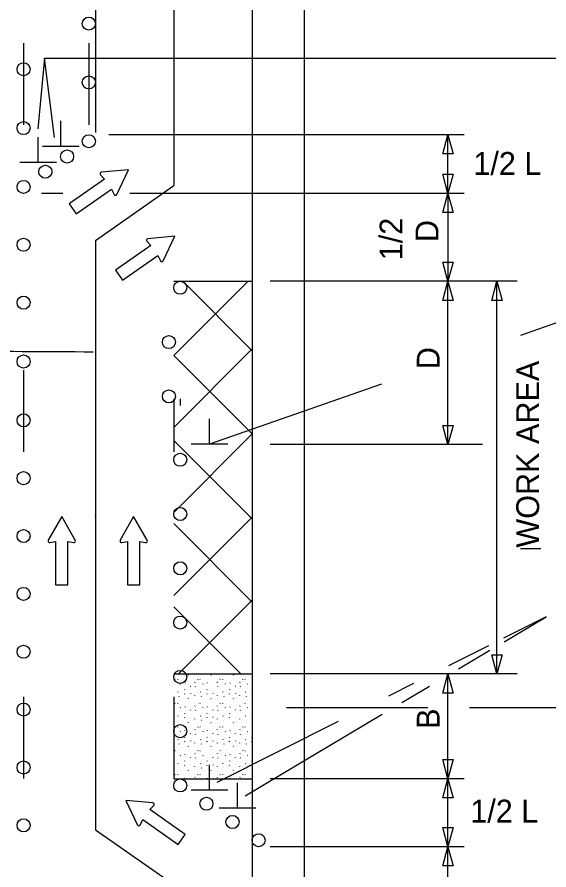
# Model space of a CAD drawing. Extents: x 16765 to 18475, y 6981 to 8262.
# Drawn here: x 17041.1 to 17204, y 7635.5 to 7896.5 of the extents above; entities that cross this region are included whole.
import ezdxf

# ---------------------------------------------------------------- set-up
doc = ezdxf.new("R2010")
doc.units = 0
for name, color, linetype in [('ALI_LEGAL_EX', 7, 'Continuous'), ('MT_SCRATCH_LEVEL_A', 7, 'Continuous'), ('MT_SCRATCH_LEVEL_E', 7, 'Continuous'), ('PAVT_EDGE_EX', 7, 'Continuous'), ('TRAFFIC_SIGNS_PR', 7, 'Continuous'), ('TYPICAL_TEXT_DIMEN_PR', 7, 'Continuous')]:
    doc.layers.add(name, color=color, linetype=linetype)

msp = doc.modelspace()

# ---------------------------------------------------------------- linework, layer by layer
at = {"layer": 'ALI_LEGAL_EX'}
for points in [[(17043.08, 7888.47), (17043.08, 7863.47)], [(17063.08, 7888.47), (17063.08, 7863.47)], [(17089.08, 7888.47), (17089.08, 7863.81)], [(17043.08, 7788.47), (17043.08, 7763.47)], [(17089.08, 7779.65), (17089.08, 7763.47)], [(17091.08, 7779.65), (17091.08, 7777.65)], [(17043.08, 7688.47), (17043.08, 7663.47)], [(17089.08, 7688.47), (17089.08, 7663.47)]]:
    msp.add_lwpolyline(points, dxfattribs=at)
at = {"layer": 'MT_SCRATCH_LEVEL_A'}
for p, q in [((17089.08, 7815.65), (17113.08, 7815.65)), ((17089.09, 7792.92), (17111.83, 7815.65)), ((17113.08, 7794.39), (17091.82, 7815.65)), ((17089.08, 7770.93), (17113.08, 7794.93)), ((17113.08, 7768.93), (17089.08, 7792.93)), ((17089.08, 7744.93), (17113.08, 7768.93)), ((17113.08, 7742.94), (17089.08, 7766.94)), ((17089.08, 7719.48), (17113.08, 7743.48)), ((17113.08, 7717.48), (17089.08, 7741.48)), ((17090.54, 7695.48), (17113.08, 7718.02)), ((17109.63, 7695.48), (17089.08, 7716.03)), ((17089.08, 7695.48), (17113.08, 7695.48)), ((17089.46, 7693.88), (17089.51, 7693.8)), ((17090.19, 7693.85), (17090.24, 7693.78)), ((17093.56, 7695.12), (17093.61, 7695.24)), ((17096.34, 7693.88), (17096.39, 7693.8)), ((17097.08, 7693.85), (17097.13, 7693.78)), ((17100.45, 7695.12), (17100.5, 7695.24)), ((17103.23, 7693.88), (17103.28, 7693.8)), ((17103.97, 7693.85), (17104.02, 7693.78)), ((17107.33, 7695.12), (17107.39, 7695.24)), ((17110.12, 7693.88), (17110.17, 7693.8)), ((17110.85, 7693.85), (17110.91, 7693.78)), ((17091.06, 7692.47), (17091.11, 7692.4)), ((17092.51, 7692.62), (17092.56, 7692.74)), ((17094.13, 7691.8), (17094.18, 7691.72)), ((17095.58, 7692.92), (17095.63, 7693.04)), ((17095.66, 7691.66), (17095.71, 7691.58)), ((17097.95, 7692.47), (17098, 7692.4)), ((17099.4, 7692.62), (17099.45, 7692.74)), ((17101.02, 7691.8), (17101.07, 7691.72)), ((17102.47, 7692.92), (17102.52, 7693.04)), ((17102.55, 7691.66), (17102.6, 7691.58)), ((17104.84, 7692.47), (17104.89, 7692.4)), ((17106.28, 7692.62), (17106.34, 7692.74)), ((17107.9, 7691.8), (17107.96, 7691.72)), ((17109.35, 7692.92), (17109.4, 7693.04)), ((17109.43, 7691.66), (17109.49, 7691.58)), ((17111.72, 7692.47), (17111.78, 7692.4)), ((17090.41, 7689.87), (17090.46, 7689.98)), ((17090.6, 7688.67), (17090.65, 7688.59)), ((17092.34, 7690.74), (17092.39, 7690.66)), ((17092.38, 7689.34), (17092.43, 7689.45)), ((17094.18, 7689.59), (17094.23, 7689.51)), ((17095.46, 7689.01), (17095.47, 7688.89)), ((17097.3, 7689.87), (17097.35, 7689.98)), ((17097.49, 7688.67), (17097.54, 7688.59)), ((17099.22, 7690.74), (17099.28, 7690.66)), ((17099.27, 7689.34), (17099.32, 7689.45)), ((17101.06, 7689.59), (17101.12, 7689.51)), ((17102.35, 7689.01), (17102.36, 7688.89)), ((17104.19, 7689.87), (17104.24, 7689.98)), ((17104.38, 7688.67), (17104.43, 7688.59)), ((17106.11, 7690.74), (17106.16, 7690.66)), ((17106.15, 7689.34), (17106.21, 7689.45)), ((17107.95, 7689.59), (17108, 7689.51)), ((17109.23, 7689.01), (17109.25, 7688.89)), ((17111.08, 7689.87), (17111.13, 7689.98)), ((17111.26, 7688.67), (17111.31, 7688.59)), ((17113, 7690.74), (17113.05, 7690.66)), ((17113.04, 7689.34), (17113.1, 7689.45)), ((17089.46, 7686.6), (17089.51, 7686.52)), ((17090.19, 7686.57), (17090.24, 7686.49)), ((17093.56, 7687.83), (17093.61, 7687.95)), ((17095.58, 7685.64), (17095.63, 7685.75)), ((17096.34, 7686.6), (17096.39, 7686.52)), ((17097.08, 7686.57), (17097.13, 7686.49)), ((17100.45, 7687.83), (17100.5, 7687.95)), ((17102.47, 7685.64), (17102.52, 7685.75)), ((17103.23, 7686.6), (17103.28, 7686.52)), ((17103.97, 7686.57), (17104.02, 7686.49)), ((17107.33, 7687.83), (17107.39, 7687.95)), ((17109.35, 7685.64), (17109.4, 7685.75)), ((17110.12, 7686.6), (17110.17, 7686.52)), ((17110.85, 7686.57), (17110.91, 7686.49)), ((17091.06, 7685.19), (17091.11, 7685.11)), ((17092.34, 7683.45), (17092.39, 7683.37)), ((17092.51, 7685.34), (17092.56, 7685.46)), ((17094.13, 7684.51), (17094.18, 7684.43)), ((17095.66, 7684.37), (17095.71, 7684.29)), ((17097.95, 7685.19), (17098, 7685.11)), ((17099.22, 7683.45), (17099.28, 7683.37)), ((17099.4, 7685.34), (17099.45, 7685.46)), ((17101.02, 7684.51), (17101.07, 7684.43)), ((17102.55, 7684.37), (17102.6, 7684.29)), ((17104.84, 7685.19), (17104.89, 7685.11)), ((17106.11, 7683.45), (17106.16, 7683.37)), ((17106.28, 7685.34), (17106.34, 7685.46)), ((17107.9, 7684.51), (17107.96, 7684.43)), ((17109.43, 7684.37), (17109.49, 7684.29)), ((17111.72, 7685.19), (17111.78, 7685.11)), ((17113, 7683.45), (17113.05, 7683.37)), ((17090.41, 7682.58), (17090.46, 7682.7)), ((17090.6, 7681.38), (17090.65, 7681.31)), ((17092.38, 7682.05), (17092.43, 7682.17)), ((17093.56, 7680.55), (17093.61, 7680.67)), ((17094.18, 7682.3), (17094.23, 7682.22)), ((17095.46, 7681.73), (17095.47, 7681.61)), ((17097.3, 7682.58), (17097.35, 7682.7)), ((17097.49, 7681.38), (17097.54, 7681.31)), ((17099.27, 7682.05), (17099.32, 7682.17)), ((17100.45, 7680.55), (17100.5, 7680.67)), ((17101.06, 7682.3), (17101.12, 7682.22)), ((17102.35, 7681.73), (17102.36, 7681.61)), ((17104.19, 7682.58), (17104.24, 7682.7)), ((17104.38, 7681.38), (17104.43, 7681.31)), ((17106.15, 7682.05), (17106.21, 7682.17)), ((17107.33, 7680.55), (17107.39, 7680.67)), ((17107.95, 7682.3), (17108, 7682.22)), ((17109.23, 7681.73), (17109.25, 7681.61)), ((17111.08, 7682.58), (17111.13, 7682.7)), ((17111.26, 7681.38), (17111.31, 7681.31)), ((17113.04, 7682.05), (17113.1, 7682.17)), ((17089.46, 7679.31), (17089.51, 7679.24)), ((17090.19, 7679.28), (17090.24, 7679.2)), ((17091.06, 7677.9), (17091.11, 7677.83)), ((17092.51, 7678.06), (17092.56, 7678.17)), ((17095.58, 7678.35), (17095.63, 7678.47)), ((17096.34, 7679.31), (17096.39, 7679.24)), ((17097.08, 7679.28), (17097.13, 7679.2)), ((17097.95, 7677.9), (17098, 7677.83)), ((17099.4, 7678.06), (17099.45, 7678.17)), ((17102.47, 7678.35), (17102.52, 7678.47)), ((17103.23, 7679.31), (17103.28, 7679.24)), ((17103.97, 7679.28), (17104.02, 7679.2)), ((17104.84, 7677.9), (17104.89, 7677.83)), ((17106.28, 7678.06), (17106.34, 7678.17)), ((17109.35, 7678.35), (17109.4, 7678.47)), ((17110.12, 7679.31), (17110.17, 7679.24)), ((17110.85, 7679.28), (17110.91, 7679.2)), ((17111.72, 7677.9), (17111.78, 7677.83)), ((17090.41, 7675.3), (17090.46, 7675.41)), ((17092.34, 7676.17), (17092.39, 7676.09)), ((17094.13, 7677.23), (17094.18, 7677.15)), ((17095.66, 7677.09), (17095.71, 7677.01)), ((17097.3, 7675.3), (17097.35, 7675.41)), ((17099.22, 7676.17), (17099.28, 7676.09)), ((17101.02, 7677.23), (17101.07, 7677.15)), ((17102.55, 7677.09), (17102.6, 7677.01)), ((17104.19, 7675.3), (17104.24, 7675.41)), ((17106.11, 7676.17), (17106.16, 7676.09)), ((17107.9, 7677.23), (17107.96, 7677.15)), ((17109.43, 7677.09), (17109.49, 7677.01)), ((17111.08, 7675.3), (17111.13, 7675.41)), ((17113, 7676.17), (17113.05, 7676.09)), ((17090.6, 7674.1), (17090.65, 7674.02)), ((17092.38, 7674.77), (17092.43, 7674.88)), ((17093.56, 7673.26), (17093.61, 7673.38)), ((17094.18, 7675.02), (17094.23, 7674.94)), ((17095.46, 7674.44), (17095.47, 7674.32)), ((17097.49, 7674.1), (17097.54, 7674.02)), ((17099.27, 7674.77), (17099.32, 7674.88)), ((17100.45, 7673.26), (17100.5, 7673.38)), ((17101.06, 7675.02), (17101.12, 7674.94)), ((17102.35, 7674.44), (17102.36, 7674.32)), ((17104.38, 7674.1), (17104.43, 7674.02)), ((17106.15, 7674.77), (17106.21, 7674.88)), ((17107.33, 7673.26), (17107.39, 7673.38)), ((17107.95, 7675.02), (17108, 7674.94)), ((17109.23, 7674.44), (17109.25, 7674.32)), ((17111.26, 7674.1), (17111.31, 7674.02)), ((17113.04, 7674.77), (17113.1, 7674.88)), ((17089.46, 7672.03), (17089.51, 7671.95)), ((17090.19, 7672), (17090.24, 7671.92)), ((17091.06, 7670.62), (17091.11, 7670.54)), ((17092.51, 7670.77), (17092.56, 7670.89)), ((17094.13, 7669.94), (17094.18, 7669.86)), ((17095.58, 7671.07), (17095.63, 7671.18)), ((17096.34, 7672.03), (17096.39, 7671.95)), ((17097.08, 7672), (17097.13, 7671.92)), ((17097.95, 7670.62), (17098, 7670.54)), ((17101.02, 7669.94), (17101.07, 7669.86)), ((17102.47, 7671.07), (17102.52, 7671.18)), ((17103.23, 7672.03), (17103.28, 7671.95)), ((17103.97, 7672), (17104.02, 7671.92)), ((17104.84, 7670.62), (17104.89, 7670.54)), ((17106.28, 7670.77), (17106.34, 7670.89)), ((17107.9, 7669.94), (17107.96, 7669.86)), ((17109.35, 7671.07), (17109.4, 7671.18)), ((17110.12, 7672.03), (17110.17, 7671.95)), ((17110.85, 7672), (17110.91, 7671.92)), ((17111.72, 7670.62), (17111.78, 7670.54)), ((17090.41, 7668.01), (17090.46, 7668.13)), ((17092.34, 7668.88), (17092.39, 7668.8)), ((17092.38, 7667.48), (17092.43, 7667.6)), ((17094.18, 7667.73), (17094.23, 7667.65)), ((17095.66, 7669.8), (17095.71, 7669.72)), ((17097.3, 7668.01), (17097.35, 7668.13)), ((17099.22, 7668.88), (17099.28, 7668.8)), ((17099.27, 7667.48), (17099.32, 7667.6)), ((17101.06, 7667.73), (17101.12, 7667.65)), ((17102.55, 7669.8), (17102.6, 7669.72)), ((17104.19, 7668.01), (17104.24, 7668.13)), ((17106.11, 7668.88), (17106.16, 7668.8)), ((17106.15, 7667.48), (17106.21, 7667.6)), ((17107.95, 7667.73), (17108, 7667.65)), ((17109.43, 7669.8), (17109.49, 7669.72)), ((17111.08, 7668.01), (17111.13, 7668.13)), ((17113, 7668.88), (17113.05, 7668.8)), ((17113.04, 7667.48), (17113.1, 7667.6)), ((17089.46, 7664.74), (17089.51, 7664.66)), ((17090.19, 7664.71), (17090.24, 7664.64)), ((17090.6, 7666.81), (17090.65, 7666.74)), ((17093.56, 7665.98), (17093.61, 7666.1)), ((17095.46, 7667.16), (17095.47, 7667.04)), ((17096.34, 7664.74), (17096.39, 7664.66)), ((17097.08, 7664.71), (17097.13, 7664.64)), ((17097.49, 7666.81), (17097.54, 7666.74)), ((17100.45, 7665.98), (17100.5, 7666.1)), ((17102.35, 7667.16), (17102.36, 7667.04)), ((17103.23, 7664.74), (17103.28, 7664.66)), ((17103.97, 7664.71), (17104.02, 7664.64)), ((17104.38, 7666.81), (17104.43, 7666.74)), ((17107.33, 7665.98), (17107.39, 7666.1)), ((17109.23, 7667.16), (17109.25, 7667.04)), ((17110.12, 7664.74), (17110.17, 7664.66)), ((17110.85, 7664.71), (17110.91, 7664.64)), ((17111.26, 7666.81), (17111.31, 7666.74)), ((17089.08, 7663.42), (17113.08, 7663.42)), ((17092.51, 7663.49), (17092.56, 7663.6)), ((17095.58, 7663.78), (17095.63, 7663.9)), ((17099.4, 7663.49), (17099.45, 7663.6)), ((17102.47, 7663.78), (17102.52, 7663.9)), ((17106.28, 7663.49), (17106.34, 7663.6)), ((17109.35, 7663.78), (17109.4, 7663.9))]:
    msp.add_line(p, q, dxfattribs=at)
at = {"layer": 'MT_SCRATCH_LEVEL_E'}
for p, q in [((17066.62, 7848.2), (17067.89, 7846.93)), ((17066.62, 7848.2), (17067.89, 7846.93)), ((17075.19, 7849.77), (17066.9, 7848.99)), ((17075.19, 7849.77), (17066.9, 7848.99)), ((17071.63, 7842.22), (17075.19, 7849.77)), ((17071.63, 7842.22), (17075.19, 7849.77)), ((17067.89, 7846.93), (17057.02, 7839.34)), ((17067.89, 7846.93), (17057.02, 7839.34)), ((17059.17, 7836.27), (17070.03, 7843.86)), ((17059.17, 7836.27), (17070.03, 7843.86)), ((17070.03, 7843.86), (17070.79, 7842.22)), ((17070.03, 7843.86), (17070.79, 7842.22)), ((17057.02, 7839.34), (17059.17, 7836.27)), ((17057.02, 7839.34), (17059.17, 7836.27)), ((17089.39, 7829.44), (17081.1, 7828.67)), ((17089.39, 7829.44), (17081.1, 7828.67)), ((17085.82, 7821.9), (17089.39, 7829.44)), ((17085.82, 7821.9), (17089.39, 7829.44)), ((17082.09, 7826.61), (17071.22, 7819.01)), ((17082.09, 7826.61), (17071.22, 7819.01)), ((17080.81, 7827.88), (17082.09, 7826.61)), ((17080.81, 7827.88), (17082.09, 7826.61)), ((17073.36, 7815.95), (17084.23, 7823.54)), ((17073.36, 7815.95), (17084.23, 7823.54)), ((17084.23, 7823.54), (17084.99, 7821.9)), ((17084.23, 7823.54), (17084.99, 7821.9)), ((17071.22, 7819.01), (17073.36, 7815.95)), ((17071.22, 7819.01), (17073.36, 7815.95)), ((17054.76, 7743.64), (17050.65, 7736.4)), ((17054.76, 7743.64), (17050.65, 7736.4)), ((17058.91, 7736.4), (17054.76, 7743.64)), ((17058.91, 7736.4), (17054.76, 7743.64)), ((17076.8, 7743.64), (17072.69, 7736.4)), ((17076.8, 7743.64), (17072.69, 7736.4)), ((17080.94, 7736.4), (17076.8, 7743.64)), ((17080.94, 7736.4), (17076.8, 7743.64)), ((17051.14, 7735.72), (17052.91, 7736.03)), ((17051.14, 7735.72), (17052.91, 7736.03)), ((17052.91, 7736.03), (17052.91, 7722.78)), ((17052.91, 7736.03), (17052.91, 7722.78)), ((17056.65, 7722.78), (17056.65, 7736.03)), ((17056.65, 7736.03), (17058.43, 7735.72)), ((17056.65, 7722.78), (17056.65, 7736.03)), ((17056.65, 7736.03), (17058.43, 7735.72)), ((17073.17, 7735.72), (17074.95, 7736.03)), ((17073.17, 7735.72), (17074.95, 7736.03)), ((17074.95, 7736.03), (17074.95, 7722.78)), ((17074.95, 7736.03), (17074.95, 7722.78)), ((17078.69, 7722.78), (17078.69, 7736.03)), ((17078.69, 7736.03), (17080.47, 7735.72)), ((17078.69, 7722.78), (17078.69, 7736.03)), ((17078.69, 7736.03), (17080.47, 7735.72)), ((17052.91, 7722.78), (17056.65, 7722.78)), ((17052.91, 7722.78), (17056.65, 7722.78)), ((17074.95, 7722.78), (17078.69, 7722.78)), ((17074.95, 7722.78), (17078.69, 7722.78)), ((17074.41, 7656.79), (17077.99, 7649.27)), ((17082.72, 7656.04), (17074.41, 7656.79)), ((17074.41, 7656.79), (17077.99, 7649.27)), ((17082.72, 7656.04), (17074.41, 7656.79)), ((17081.73, 7653.98), (17083.01, 7655.26)), ((17081.73, 7653.98), (17083.01, 7655.26)), ((17092.6, 7646.39), (17081.73, 7653.98)), ((17092.6, 7646.39), (17081.73, 7653.98)), ((17078.83, 7649.27), (17079.59, 7650.91)), ((17078.83, 7649.27), (17079.59, 7650.91)), ((17079.59, 7650.91), (17090.46, 7643.32)), ((17079.59, 7650.91), (17090.46, 7643.32)), ((17090.46, 7643.32), (17092.6, 7646.39)), ((17090.46, 7643.32), (17092.6, 7646.39))]:
    msp.add_line(p, q, dxfattribs=at)
for centre, start, end in [((17066.95, 7848.53), 95.3561, 224.895), ((17066.95, 7848.53), 95.3561, 224.895), ((17071.21, 7842.43), 204.9674, 334.7043), ((17071.21, 7842.43), 204.9674, 334.7043), ((17081.14, 7828.21), 95.3561, 224.895), ((17081.14, 7828.21), 95.3561, 224.895), ((17085.4, 7822.11), 204.9674, 334.7043), ((17085.4, 7822.11), 204.9674, 334.7043), ((17051.06, 7736.18), 150.4248, 279.9638), ((17051.06, 7736.18), 150.4248, 279.9638), ((17058.5, 7736.18), 260.0362, 29.7731), ((17058.5, 7736.18), 260.0362, 29.7731), ((17073.09, 7736.18), 150.4248, 279.9638), ((17073.09, 7736.18), 150.4248, 279.9638), ((17080.54, 7736.18), 260.0362, 29.7731), ((17080.54, 7736.18), 260.0362, 29.7731), ((17082.67, 7655.58), 315.105, 84.8419), ((17082.67, 7655.58), 315.105, 84.8419), ((17078.41, 7649.48), 205.4936, 335.0326), ((17078.41, 7649.48), 205.4936, 335.0326)]:
    msp.add_arc(centre, 0.463, start, end, dxfattribs=at)
at = {"layer": 'PAVT_EDGE_EX'}
for p, q in [((17065.08, 8196.54), (17065.08, 7861.14)), ((17113.08, 8196.54), (17113.08, 7351.89)), ((17129.08, 8196.54), (17129.08, 7351.89)), ((17089.08, 7909.01), (17089.08, 7844.93)), ((17065.08, 7828.16), (17089.08, 7844.93)), ((17065.08, 7828.16), (17065.08, 7822.94)), ((17065.08, 7822.94), (17065.08, 7647.81)), ((17065.08, 7743.64), (17065.08, 7743.9)), ((17065.08, 7647.81), (17089.08, 7631.05))]:
    msp.add_line(p, q, dxfattribs=at)
at = {"layer": 'TRAFFIC_SIGNS_PR'}
for centre in [(17063.08, 7894.48), (17043.08, 7880.51), (17063.08, 7876.48), (17043.08, 7862.51), (17063.08, 7858.48), (17056.41, 7853.82), (17049.75, 7849.17), (17043.08, 7844.51), (17043.08, 7844.51), (17043.08, 7826.81), (17091.08, 7813.65), (17043.08, 7809.1), (17087.6, 7797.04), (17043.08, 7791.1), (17087.6, 7780.43), (17043.08, 7773.1), (17091.08, 7761.04), (17043.08, 7755.4), (17091.08, 7744.43), (17043.08, 7737.69), (17091.08, 7727.81), (17043.08, 7719.99), (17091.08, 7711.2), (17043.08, 7702.28), (17091.08, 7694.59), (17043.08, 7684.58), (17091.08, 7677.98), (17043.08, 7666.87), (17091.08, 7661.37), (17091.08, 7661.37), (17099.08, 7655.78), (17107.08, 7650.19), (17043.08, 7649.17), (17115.08, 7644.61)]:
    msp.add_circle(centre, 2, dxfattribs=at)
at = {"layer": 'TYPICAL_TEXT_DIMEN_PR'}
for p, q in [((17049.47, 7883.9), (17047.41, 7862.24)), ((17049.47, 7883.9), (17220.2, 7883.9)), ((17052.55, 7859.66), (17049.47, 7883.9)), ((17054.46, 7856.91), (17054.46, 7864.7)), ((17178.08, 7860.48), (17069.15, 7860.48)), ((17171.51, 7854.62), (17173.08, 7860.48)), ((17173.08, 7842.51), (17173.08, 7860.48)), ((17173.08, 7860.48), (17174.65, 7854.62)), ((17047.53, 7851.96), (17047.53, 7859.75)), ((17060.08, 7856.91), (17048.83, 7856.91)), ((17173.08, 7854.62), (17171.51, 7854.62)), ((17174.65, 7854.62), (17173.08, 7854.62)), ((17053.15, 7851.96), (17041.9, 7851.96)), ((17173.08, 7842.51), (17171.51, 7848.37)), ((17171.51, 7848.37), (17173.08, 7848.37)), ((17173.08, 7848.37), (17174.65, 7848.37)), ((17174.65, 7848.37), (17173.08, 7842.51)), ((17055.08, 7842.51), (17048.53, 7842.51)), ((17178.08, 7842.51), (17075.61, 7842.51)), ((17171.51, 7836.65), (17173.08, 7842.51)), ((17173.08, 7842.51), (17174.65, 7836.65)), ((17173.08, 7842.51), (17173.08, 7815.65)), ((17173.08, 7836.65), (17171.51, 7836.65)), ((17174.65, 7836.65), (17173.08, 7836.65)), ((17173.08, 7815.65), (17171.51, 7821.51)), ((17171.51, 7821.51), (17173.08, 7821.51)), ((17173.08, 7821.51), (17174.65, 7821.51)), ((17174.65, 7821.51), (17173.08, 7815.65)), ((17194.29, 7815.65), (17118.58, 7815.65)), ((17171.51, 7809.79), (17173.08, 7815.65)), ((17173.08, 7765.65), (17173.08, 7815.65)), ((17173.08, 7815.65), (17174.65, 7809.79)), ((17186.51, 7809.79), (17188.08, 7815.65)), ((17188.08, 7695.48), (17188.08, 7815.65)), ((17188.08, 7815.65), (17189.65, 7809.79)), ((17173.08, 7809.79), (17171.51, 7809.79)), ((17174.65, 7809.79), (17173.08, 7809.79)), ((17188.08, 7809.79), (17186.51, 7809.79)), ((17189.65, 7809.79), (17188.08, 7809.79)), ((17226.14, 7809.86), (17195.34, 7799.09)), ((17152.72, 7784.19), (17100.05, 7765.77)), ((17100.05, 7765.77), (17100.05, 7773.56)), ((17173.08, 7765.65), (17171.51, 7771.51)), ((17171.51, 7771.51), (17173.08, 7771.51)), ((17173.08, 7771.51), (17174.65, 7771.51)), ((17174.65, 7771.51), (17173.08, 7765.65)), ((17105.68, 7765.77), (17094.43, 7765.77)), ((17183.62, 7765.65), (17118.58, 7765.65)), ((17195.3, 7733.92), (17201.57, 7733.92)), ((17203.14, 7713), (17190.04, 7706.41)), ((17190.27, 7705.36), (17203.14, 7713)), ((17185.47, 7704.12), (17173.22, 7697.95)), ((17176.28, 7697.04), (17185.92, 7702.77)), ((17188.08, 7695.48), (17186.51, 7701.34)), ((17186.51, 7701.34), (17188.08, 7701.34)), ((17188.08, 7701.34), (17189.65, 7701.34)), ((17189.65, 7701.34), (17188.08, 7695.48)), ((17194.29, 7695.48), (17118.58, 7695.48)), ((17171.51, 7689.61), (17173.08, 7695.48)), ((17173.08, 7663.42), (17173.08, 7695.48)), ((17173.08, 7695.48), (17174.65, 7689.61)), ((17162.54, 7692.58), (17154.83, 7688.7)), ((17158.95, 7686.73), (17167.4, 7691.76)), ((17173.08, 7689.61), (17171.51, 7689.61)), ((17174.65, 7689.61), (17173.08, 7689.61)), ((17110.99, 7658.22), (17152.91, 7683.14)), ((17123.64, 7685.21), (17166.91, 7685.21)), ((17179.67, 7685.21), (17220.2, 7685.21)), ((17139.46, 7680.97), (17102.24, 7662.24)), ((17100.05, 7659.91), (17100.05, 7667.7)), ((17173.08, 7663.42), (17171.51, 7669.28)), ((17171.51, 7669.28), (17173.08, 7669.28)), ((17173.08, 7669.28), (17174.65, 7669.28)), ((17174.65, 7669.28), (17173.08, 7663.42)), ((17108.65, 7654.4), (17108.65, 7662.19)), ((17178.08, 7663.42), (17118.58, 7663.42)), ((17171.51, 7657.56), (17173.08, 7663.42)), ((17173.08, 7663.42), (17174.65, 7657.56)), ((17173.08, 7642.61), (17173.08, 7663.42)), ((17105.68, 7659.91), (17094.43, 7659.91)), ((17173.08, 7657.56), (17171.51, 7657.56)), ((17174.65, 7657.56), (17173.08, 7657.56)), ((17114.27, 7654.4), (17103.02, 7654.4)), ((17173.08, 7642.61), (17171.51, 7648.47)), ((17171.51, 7648.47), (17173.08, 7648.47)), ((17173.08, 7648.47), (17174.65, 7648.47)), ((17174.65, 7648.47), (17173.08, 7642.61)), ((17178.08, 7642.61), (17118.58, 7642.61)), ((17171.51, 7636.74), (17173.08, 7642.61)), ((17173.08, 7642.61), (17174.65, 7636.74)), ((17173.08, 7592.61), (17173.08, 7642.61)), ((17173.08, 7636.74), (17171.51, 7636.74)), ((17174.65, 7636.74), (17173.08, 7636.74))]:
    msp.add_line(p, q, dxfattribs=at)
msp.add_open_spline([(17064.36, 7793.98), (16979.58, 7793.98), (16979.58, 7801.85), (17015.54, 7801.85), (17015.54, 7808.01), (16967.25, 7808.01), (16963.31, 7808.01)], degree=2, dxfattribs=at)

# ---------------------------------------------------------------- texts
for p in [(17180.86, 7848.2), (17179.92, 7650.02)]:
    msp.add_text('1/2 L', height=7, dxfattribs=at).set_placement(p)
for s, p in [('1/2', (17159.15, 7822.07)), ('D', (17170.15, 7827.64)), ('D', (17170.52, 7788.74)), ('WORK AREA', (17201, 7734.13)), ('B', (17170.52, 7678.68))]:
    msp.add_text(s, height=7, rotation=90, dxfattribs=at).set_placement(p)

doc.saveas('drawing.dxf')
